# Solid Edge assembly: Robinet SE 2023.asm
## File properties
Author: Ionut
Template: Iso Metric Assembly.asm
Last saved by: Ionut
Revision: 2
Application: Solid Edge
Username: Ionut
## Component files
Handle01.par
NutM15.par
Body01.par
LValve.par
RValve.par
ValveShaft.par
TopFlange.par
SideFlange.par
ScrewM8.par
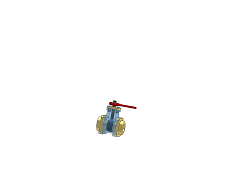
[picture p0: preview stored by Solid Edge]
